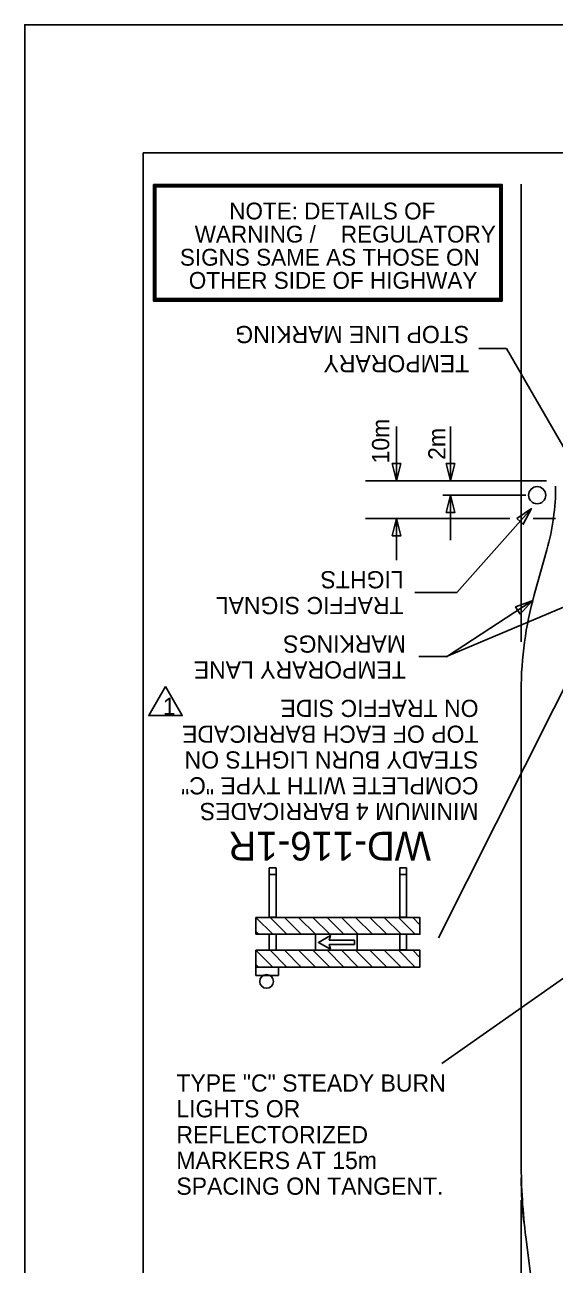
# Model space of a CAD drawing. Extents: x 2179 to 2395, y 134 to 413.
# Drawn here: x 2178.7 to 2223.4, y 308.2 to 412.8 of the extents above; entities that cross this region are included whole.
import ezdxf

# ---------------------------------------------------------------- set-up
doc = ezdxf.new("R2010")
doc.units = 0
for name, color, linetype in [('Level 1', 7, 'Continuous'), ('Level 10', 7, 'Continuous'), ('Level 44', 7, 'Continuous'), ('Level 5', 7, 'Continuous'), ('Level 60', 7, 'Continuous'), ('Level 7', 7, 'Continuous')]:
    doc.layers.add(name, color=color, linetype=linetype)

# ---------------------------------------------------------------- blocks, each defined once
blk = doc.blocks.new('REV1')
at = {"layer": 'Level 1'}
blk.add_lwpolyline([(0.114, 1.689), (-1.305, -0.781), (1.533, -0.781)], close=True, dxfattribs=at)
blk.add_text('1', height=1.448, rotation=360, dxfattribs=at).set_placement((-0.113, -0.724))

msp = doc.modelspace()

# ---------------------------------------------------------------- linework, layer by layer
at = {"layer": 'Level 10'}
for p, q in [((2220.64, 360.72), (2220.64, 399.31)), ((2217.08, 385.45), (2219.41, 385.45)), ((2219.41, 385.45), (2225.85, 374.3)), ((2210.12, 374.3), (2210.12, 378.89)), ((2214.68, 374.3), (2214.68, 378.89)), ((2222.79, 374.3), (2207.51, 374.3)), ((2221.02, 373.08), (2214.04, 373.08)), ((2214.68, 369.29), (2214.68, 373.08)), ((2219.69, 371.11), (2207.51, 371.11)), ((2210.12, 367.61), (2210.12, 371.11)), ((2215.2, 364.87), (2221.5, 371.95)), ((2223.55, 371.11), (2221.66, 371.11)), ((2221.75, 364.68), (2222.81, 368.47)), ((2211.67, 364.87), (2215.2, 364.87)), ((2221.58, 364.16), (2214.33, 359.46)), ((2214.35, 359.48), (2226.33, 364.54)), ((2227.11, 362.5), (2213.67, 335.74)), ((2214.33, 359.48), (2211.99, 359.48)), ((2220.64, 353.23), (2220.64, 356.61)), ((2220.64, 321.3), (2220.64, 353.23)), ((2213.93, 325.16), (2226.21, 333.75)), ((2220.64, 316.78), (2220.64, 321.81)), ((2220.64, 178.24), (2220.64, 313.63)), ((2223.31, 292.52), (2221.04, 310.52))]:
    msp.add_line(p, q, dxfattribs=at)
for points in [[(2214.32, 371.62), (2214.68, 373.08), (2215.04, 371.62)], [(2209.76, 369.66), (2210.12, 371.11), (2210.49, 369.66)], [(2200.16, 333.27), (2198.25, 333.27), (2198.25, 332.58), (2200.16, 332.58)]]:
    msp.add_lwpolyline(points, close=True, dxfattribs=at)
msp.add_circle((2199.15, 332.07), 0.576, dxfattribs=at)
at = {"layer": 'Level 44'}
msp.add_circle((2221.99, 373.08), 0.726, dxfattribs=at)
at = {"layer": 'Level 5'}
for p, q in [((2199.95, 341.08), (2199.38, 341.08)), ((2210.96, 341.08), (2210.39, 341.08)), ((2212.09, 337.46), (2198.25, 337.46)), ((2198.25, 337.46), (2198.25, 336.05)), ((2212.09, 337.46), (2212.09, 336.05)), ((2212.09, 336.05), (2198.25, 336.05)), ((2210.96, 336.05), (2210.67, 336.05)), ((2198.25, 334.7), (2198.25, 333.28)), ((2212.09, 334.7), (2198.25, 334.7)), ((2199.38, 334.73), (2199.38, 334.7)), ((2203.3, 334.71), (2206.79, 334.71)), ((2203.3, 334.71), (2206.79, 334.71)), ((2210.39, 334.73), (2210.39, 334.7)), ((2212.09, 334.7), (2212.09, 333.28)), ((2212.09, 333.28), (2198.25, 333.28)), ((2200.52, 333.27), (2201.09, 333.27)), ((2210.96, 333.28), (2210.67, 333.28))]:
    msp.add_line(p, q, dxfattribs=at)
for points in [[(2210.49, 375.75), (2210.12, 374.3), (2209.76, 375.75)], [(2215.04, 375.75), (2214.68, 374.3), (2214.32, 375.75)], [(2220.27, 371.11), (2221.5, 371.95), (2220.81, 370.63)], [(2220.16, 363.67), (2221.58, 364.16), (2220.56, 363.06)], [(2199.38, 337.48), (2199.95, 337.48), (2199.95, 341.65), (2199.38, 341.65)], [(2210.39, 337.48), (2210.96, 337.48), (2210.96, 341.65), (2210.39, 341.65)], [(2199.67, 336.05), (2200.87, 336.05), (2199.45, 337.46), (2198.25, 337.46)], [(2202.07, 336.05), (2203.28, 336.05), (2201.86, 337.46), (2200.66, 337.46)], [(2204.48, 336.05), (2205.68, 336.05), (2204.27, 337.46), (2203.06, 337.46)], [(2206.89, 336.05), (2208.09, 336.05), (2206.67, 337.46), (2205.47, 337.46)], [(2209.29, 336.05), (2210.5, 336.05), (2209.08, 337.46), (2207.88, 337.46)], [(2211.7, 336.05), (2212.09, 336.05), (2212.09, 336.86), (2211.49, 337.46), (2210.28, 337.46)], [(2198.25, 336.05), (2198.46, 336.05), (2198.25, 336.26)], [(2199.38, 334.73), (2199.95, 334.7), (2199.95, 336.05), (2199.38, 336.05)], [(2206.79, 334.71), (2206.79, 336.05), (2203.28, 336.05), (2203.28, 334.71)], [(2206.56, 335.18), (2206.56, 335.55), (2204.44, 335.55), (2204.55, 335.95), (2203.53, 335.37), (2204.55, 334.78), (2204.44, 335.18)], [(2206.56, 335.18), (2206.56, 335.55), (2204.44, 335.55), (2204.55, 335.95), (2203.53, 335.37), (2204.55, 334.78), (2204.44, 335.18)], [(2210.39, 334.73), (2210.96, 334.73), (2210.96, 336.05), (2210.39, 336.05)], [(2199.67, 333.28), (2200.87, 333.28), (2199.45, 334.7), (2198.25, 334.7)], [(2202.07, 333.28), (2203.28, 333.28), (2201.86, 334.7), (2200.66, 334.7)], [(2204.48, 333.28), (2205.68, 333.28), (2204.27, 334.7), (2203.06, 334.7)], [(2206.89, 333.28), (2208.09, 333.28), (2206.67, 334.7), (2205.47, 334.7)], [(2209.29, 333.28), (2210.5, 333.28), (2209.08, 334.7), (2207.88, 334.7)], [(2211.7, 333.28), (2212.09, 333.28), (2212.09, 334.09), (2211.49, 334.7), (2210.28, 334.7)], [(2198.46, 333.28), (2198.25, 333.28), (2198.25, 333.5)]]:
    msp.add_lwpolyline(points, close=True, dxfattribs=at)
for points in [[(2198.25, 337.46), (2199.67, 336.05), (2198.46, 336.05), (2198.25, 336.26), (2198.25, 337.46)], [(2200.66, 337.46), (2202.07, 336.05), (2200.87, 336.05), (2199.45, 337.46), (2200.66, 337.46)], [(2203.06, 337.46), (2204.48, 336.05), (2203.28, 336.05), (2201.86, 337.46), (2203.06, 337.46)], [(2205.47, 337.46), (2206.89, 336.05), (2205.68, 336.05), (2204.27, 337.46), (2205.47, 337.46)], [(2209.29, 336.05), (2208.09, 336.05), (2206.67, 337.46), (2207.88, 337.46), (2209.29, 336.05)], [(2211.7, 336.05), (2210.5, 336.05), (2209.08, 337.46), (2210.28, 337.46), (2211.7, 336.05)], [(2212.09, 336.86), (2211.49, 337.46), (2212.09, 337.46), (2212.09, 336.86)], [(2198.25, 334.7), (2199.67, 333.28), (2198.46, 333.28), (2198.25, 333.5), (2198.25, 334.7)], [(2200.66, 334.7), (2202.07, 333.28), (2200.87, 333.28), (2199.45, 334.7), (2200.66, 334.7)], [(2203.06, 334.7), (2204.48, 333.28), (2203.28, 333.28), (2201.86, 334.7), (2203.06, 334.7)], [(2205.47, 334.7), (2206.89, 333.28), (2205.68, 333.28), (2204.27, 334.7), (2205.47, 334.7)], [(2209.29, 333.28), (2208.09, 333.28), (2206.67, 334.7), (2207.88, 334.7), (2209.29, 333.28)], [(2211.7, 333.28), (2210.5, 333.28), (2209.08, 334.7), (2210.28, 334.7), (2211.7, 333.28)], [(2212.09, 334.09), (2211.49, 334.7), (2212.09, 334.7), (2212.09, 334.09)]]:
    msp.add_lwpolyline(points, dxfattribs=at)
for centre, radius, start, end in [((2203.55, 373.85), 20, 344.3937, 0), ((2250.64, 356.61), 30, 164.3937, 180), ((2270.64, 316.78), 50, 180, 187.1968), ((2250.64, 315.52), 30, 180, 187.1968)]:
    msp.add_arc(centre, radius, start, end, dxfattribs=at)
at = {"layer": 'Level 60'}
for points in [[(2394.75, 412.76), (2178.75, 412.76), (2178.75, 133.76), (2394.75, 133.76)], [(2375.62, 401.95), (2188.75, 401.95), (2188.75, 144.57), (2375.62, 144.57)]]:
    msp.add_lwpolyline(points, close=True, dxfattribs=at)
at = {"layer": 'Level 7'}
for points in [[(2189.62, 399.29), (2219.03, 399.29), (2219.03, 389.46), (2189.62, 389.46)], [(2189.72, 399.19), (2218.93, 399.19), (2218.93, 389.56), (2189.72, 389.56)], [(2189.82, 399.09), (2218.83, 399.09), (2218.83, 389.66), (2189.82, 389.66)]]:
    msp.add_lwpolyline(points, close=True, dxfattribs=at)

# ---------------------------------------------------------------- block references
at = {"layer": 'Level 1'}
msp.add_blockref('REV1', (2190.51, 355.27), dxfattribs=at)

# ---------------------------------------------------------------- texts
at = {"layer": 'Level 10'}
for s, height, rotation, p in [('STOP LINE MARKING', 1.4514, 180, (2216.25, 387.36)), ('TEMPORARY', 1.451, 180, (2216.25, 384.9)), ('10m', 1.451, 90, (2209.5, 375.76)), ('2m', 1.451, 90, (2214.25, 376.06)), ('LIGHTS', 1.451, 180, (2210.72, 366.68)), ('TRAFFIC SIGNAL', 1.4514, 180, (2210.72, 364.5)), ('MARKINGS', 1.451, 180, (2210.91, 361.25)), ('TEMPORARY LANE', 1.4514, 180, (2210.91, 359.07)), ('ON TRAFFIC SIDE', 1.4514, 180, (2217.04, 355.83)), ('TOP OF EACH BARRICADE ', 1.4514, 180, (2217.04, 353.65)), ('STEADY BURN LIGHTS ON ', 1.4514, 180, (2217.04, 351.48)), ('COMPLETE WITH TYPE "C" ', 1.4514, 180, (2217.04, 349.3)), ('MINIMUM 4 BARRICADES', 1.4514, 180, (2217.04, 347.13)), ('WD-116-1R', 2.419, 180, (2213.02, 344.69))]:
    msp.add_text(s, height=height, rotation=rotation, dxfattribs=at).set_placement(p)
for s, height, p in [('TYPE "C" STEADY BURN ', 1.4514, (2191.54, 322.78)), ('LIGHTS OR ', 1.451, (2191.54, 320.61)), ('REFLECTORIZED ', 1.4514, (2191.54, 318.43)), ('MARKERS AT 15m ', 1.4514, (2191.54, 316.25)), ('SPACING ON TANGENT.', 1.4514, (2191.54, 314.08))]:
    msp.add_text(s, height=height, dxfattribs=at).set_placement(p)
at = {"layer": 'Level 7'}
for s, p in [('NOTE: DETAILS OF ', (2196, 396.34)), ('WARNING /    REGULATORY', (2193.09, 394.39)), ('SIGNS SAME AS THOSE ON', (2191.84, 392.44)), ('OTHER SIDE OF HIGHWAY', (2192.59, 390.49))]:
    msp.add_text(s, height=1.419, dxfattribs=at).set_placement(p)

doc.saveas('drawing.dxf')
